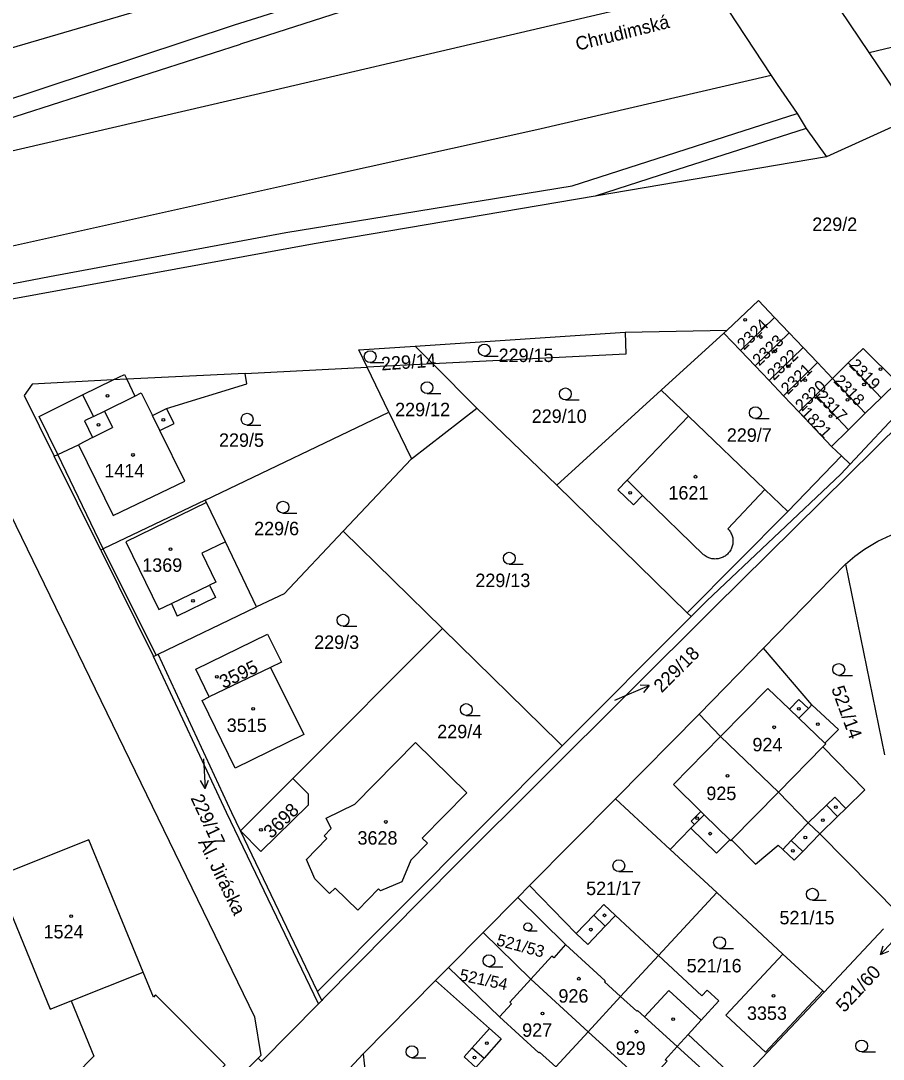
# Model space of a CAD drawing. Extents: x -679220 to -673243, y -1075091 to -1066557.
# Drawn here: x -675950 to -675840.9, y -1071652.9 to -1071521.5 of the extents above; entities that cross this region are included whole.
import ezdxf

# ---------------------------------------------------------------- set-up
doc = ezdxf.new("R2010")
doc.units = 0
for name, color, linetype in [('Hranice parcel', 7, 'Continuous'), ('Parcelní čísla', 7, 'Continuous'), ('Pop  PČ popisy', 7, 'Continuous'), ('Vnitřní kresba', 7, 'Continuous'), ('Značky budov', 7, 'Continuous'), ('Značky kultur', 7, 'Continuous')]:
    doc.layers.add(name, color=color, linetype=linetype)

msp = doc.modelspace()

# ---------------------------------------------------------------- linework, layer by layer
at = {"layer": 'Hranice parcel'}
for p, q in [((-675854.66, -1071559.03), (-675859, -1071563.2)), ((-675854.66, -1071559.03), (-675852.81, -1071560.99)), ((-675900.15, -1071562.66), (-675873.58, -1071560.89)), ((-675873.58, -1071560.89), (-675860.65, -1071560.63)), ((-675869, -1071568.25), (-675861.07, -1071561.03)), ((-675861.07, -1071561.03), (-675860.65, -1071560.63)), ((-675861.07, -1071561.03), (-675859, -1071563.2)), ((-675852.81, -1071560.99), (-675857.14, -1071565.16)), ((-675852.81, -1071560.99), (-675851.06, -1071562.83)), ((-675897.9, -1071564.92), (-675900.15, -1071562.66)), ((-675851.06, -1071562.83), (-675855.37, -1071567.02)), ((-675851.06, -1071562.83), (-675849.25, -1071564.74)), ((-675859, -1071563.2), (-675857.14, -1071565.16)), ((-675921.65, -1071566.11), (-675906.21, -1071565.34)), ((-675897.9, -1071564.92), (-675906.21, -1071565.34)), ((-675903.46, -1071571.03), (-675906.21, -1071565.34)), ((-675897.9, -1071564.92), (-675892.34, -1071570.5)), ((-675857.14, -1071565.16), (-675855.37, -1071567.02)), ((-675849.25, -1071564.74), (-675853.54, -1071568.95)), ((-675849.25, -1071564.74), (-675847.33, -1071566.77)), ((-675847.33, -1071566.77), (-675845.34, -1071564.8)), ((-675841.2, -1071569.22), (-675845.34, -1071564.8)), ((-675855.37, -1071567.02), (-675853.54, -1071568.95)), ((-675847.33, -1071566.77), (-675849.47, -1071568.88)), ((-675843.19, -1071571.17), (-675847.33, -1071566.77)), ((-675882.2, -1071580.25), (-675869, -1071568.25)), ((-675853.54, -1071568.95), (-675851.6, -1071570.98)), ((-675849.47, -1071568.88), (-675851.6, -1071570.98)), ((-675845.32, -1071573.26), (-675849.47, -1071568.88)), ((-675841.2, -1071569.22), (-675843.19, -1071571.17)), ((-675926.7, -1071582.15), (-675903.46, -1071571.03)), ((-675903.46, -1071571.03), (-675900.6, -1071576.95)), ((-675900.6, -1071576.95), (-675892.34, -1071570.5)), ((-675892.34, -1071570.5), (-675882.2, -1071580.25)), ((-675851.6, -1071570.98), (-675847.45, -1071575.35)), ((-675843.19, -1071571.17), (-675845.32, -1071573.26)), ((-675845.32, -1071573.26), (-675847.45, -1071575.35)), ((-675847.45, -1071575.35), (-675846.21, -1071576.54)), ((-675939.91, -1071588.47), (-675945.79, -1071576.58)), ((-675909.23, -1071586.08), (-675900.6, -1071576.95)), ((-675853.01, -1071583.58), (-675846.21, -1071576.54)), ((-675882.2, -1071580.25), (-675865.71, -1071596.42)), ((-675865.71, -1071596.42), (-675853.01, -1071583.58)), ((-675896.66, -1071598.42), (-675909.23, -1071586.08)), ((-675939.91, -1071588.47), (-675933.24, -1071601.95)), ((-675856.06, -1071600.88), (-675845.69, -1071590.25)), ((-675845.69, -1071590.25), (-675840.78, -1071614.39)), ((-675932.64, -1071601.66), (-675920.21, -1071595.68)), ((-675915.61, -1071617.37), (-675896.66, -1071598.42)), ((-675864.22, -1071609.24), (-675856.06, -1071600.88)), ((-675918.42, -1071603.32), (-675926.18, -1071607.06)), ((-675874.81, -1071619.96), (-675864.22, -1071609.24)), ((-675912.49, -1071644.37), (-675881.54, -1071613.27)), ((-675922.23, -1071624), (-675915.61, -1071617.37)), ((-675885.67, -1071630.95), (-675874.81, -1071619.96)), ((-675874.81, -1071619.96), (-675867.88, -1071626.38)), ((-675912.49, -1071644.37), (-675922.23, -1071624)), ((-675848.96, -1071624.39), (-675839.01, -1071634.47)), ((-675867.88, -1071626.38), (-675861.99, -1071631.84)), ((-675887.15, -1071632.45), (-675885.67, -1071630.95)), ((-675891.53, -1071636.88), (-675887.15, -1071632.45)), ((-675861.99, -1071631.84), (-675869.35, -1071639.78)), ((-675861.99, -1071631.84), (-675853.61, -1071639.61)), ((-675840.91, -1071636.43), (-675848.4, -1071644.43)), ((-675895.92, -1071641.31), (-675891.53, -1071636.88)), ((-675891.53, -1071636.88), (-675885.5, -1071642.8)), ((-675853.61, -1071639.61), (-675848.57, -1071644.27)), ((-675943.67, -1071645.52), (-675934.54, -1071641.89)), ((-675897.55, -1071642.97), (-675895.92, -1071641.31)), ((-675906.72, -1071652.25), (-675897.55, -1071642.97)), ((-675885.5, -1071642.8), (-675878.24, -1071649.44)), ((-675911.96, -1071645.47), (-675912.49, -1071644.37)), ((-675848.4, -1071644.43), (-675859.1, -1071655.78)), ((-675848.57, -1071644.27), (-675848.4, -1071644.43)), ((-675911.96, -1071645.47), (-675912.38, -1071645.9)), ((-675870.95, -1071656.1), (-675878.24, -1071649.44)), ((-675915.58, -1071661.71), (-675906.72, -1071652.25))]:
    msp.add_line(p, q, dxfattribs=at)
for points in [[(-675837.15, -1071533.74), (-675838.99, -1071531.01), (-675840.42, -1071528.88), (-675842.72, -1071525.48), (-675850.05, -1071514.58), (-675853.19, -1071509.92), (-675855.42, -1071506.6)], [(-676016.9, -1071547.75), (-675987.28, -1071541.17), (-675968.47, -1071537.02), (-675954.84, -1071532.51), (-675953.23, -1071531.98), (-675923, -1071521.98), (-675892.45, -1071512.39), (-675869.31, -1071507.45)], [(-675837.15, -1071533.74), (-675848.11, -1071538.72), (-675877.36, -1071543.69), (-675912.93, -1071549.73), (-675950.9, -1071556.66), (-675972.74, -1071561.14), (-676014.26, -1071571.02)], [(-675860.65, -1071560.63), (-675856.7, -1071556.88), (-675854.66, -1071559.03)], [(-675873.58, -1071560.89), (-675873.47, -1071563.69), (-675897.9, -1071564.92)], [(-675906.21, -1071565.34), (-675907.27, -1071563.14), (-675900.15, -1071562.66)], [(-675845.34, -1071564.8), (-675843.47, -1071562.95), (-675839.16, -1071567.22), (-675841.2, -1071569.22)], [(-675846.21, -1071576.54), (-675845.1, -1071577.61), (-675838.31, -1071570.35), (-675835.37, -1071567.23), (-675832.35, -1071564.34), (-675831.77, -1071565.57)], [(-675831.77, -1071565.57), (-675862.32, -1071595.73), (-675894.88, -1071628.17), (-675911.82, -1071645.32), (-675911.96, -1071645.47)], [(-675921.65, -1071566.11), (-675936.6, -1071566.86), (-675938.34, -1071566.95), (-675948.6, -1071567.47), (-675949.58, -1071568.92), (-675945.79, -1071576.58)], [(-675945.79, -1071576.58), (-675945.34, -1071576.37), (-675942.72, -1071575.15), (-675938.34, -1071584.12), (-675929.26, -1071579.75), (-675932.44, -1071573.34), (-675930.64, -1071572.45), (-675931.58, -1071570.57), (-675921.44, -1071567.45), (-675921.65, -1071566.11)], [(-676011.87, -1071581.65), (-676010.11, -1071577.99), (-675962.74, -1071567.26), (-675958.61, -1071569.02), (-675920.48, -1071647.57), (-675919.65, -1071652.44), (-675920, -1071652.79)], [(-675853.01, -1071583.58), (-675855.88, -1071580.82), (-675865.56, -1071571.54), (-675869, -1071568.25)], [(-675926.7, -1071582.15), (-675939.59, -1071588.32), (-675939.91, -1071588.47)], [(-675920.21, -1071595.68), (-675924.13, -1071587.42), (-675926.55, -1071582.46), (-675926.7, -1071582.15)], [(-675845.69, -1071590.25), (-675844.52, -1071589.23), (-675843.28, -1071588.35), (-675841.6, -1071587.37), (-675839.97, -1071586.6), (-675838.55, -1071586.06), (-675836.65, -1071585.68), (-675834.32, -1071585.37), (-675832.14, -1071585.35), (-675828.3, -1071585.95), (-675826.58, -1071586.56), (-675824.62, -1071587.52), (-675822.57, -1071588.81), (-675821.2, -1071589.94), (-675818.99, -1071592.52)], [(-675909.23, -1071586.08), (-675916.71, -1071594), (-675920.21, -1071595.68)], [(-675881.54, -1071613.27), (-675865.23, -1071596.89), (-675865.71, -1071596.42)], [(-675881.54, -1071613.27), (-675881.98, -1071612.85), (-675896.66, -1071598.42)], [(-675926.18, -1071607.06), (-675927.9, -1071603.57), (-675918.8, -1071599.11), (-675917.06, -1071602.66), (-675918.42, -1071603.32)], [(-675848.96, -1071624.39), (-675846.7, -1071622.19), (-675845.66, -1071621.18), (-675843.24, -1071618.82), (-675848.55, -1071613.37), (-675848.2, -1071613.02), (-675848.3, -1071612.91), (-675846.58, -1071611.18), (-675849.97, -1071608.07), (-675856.06, -1071600.88)], [(-675933.24, -1071601.95), (-675932.91, -1071601.79), (-675932.64, -1071601.66)], [(-675912.38, -1071645.9), (-675923.99, -1071621.69), (-675933.24, -1071601.95)], [(-675922.23, -1071624), (-675923.31, -1071621.75), (-675932.64, -1071601.66)], [(-675918.42, -1071603.32), (-675914.23, -1071611.83), (-675922.89, -1071616.07), (-675927.1, -1071607.52), (-675926.18, -1071607.06)], [(-675864.22, -1071609.24), (-675861.5, -1071612.08), (-675854.19, -1071619.12), (-675850.4, -1071623), (-675848.96, -1071624.39)], [(-675910.24, -1071631.25), (-675910.96, -1071631.94), (-675912.82, -1071630.1), (-675913.89, -1071627.65), (-675911.29, -1071624.98), (-675911.64, -1071624.63), (-675910.74, -1071623.7), (-675911.39, -1071622.42), (-675907.78, -1071620.63), (-675900.1, -1071612.84), (-675893.61, -1071619.2), (-675899.23, -1071624.94), (-675898.59, -1071625.56), (-675900.68, -1071627.72), (-675901.81, -1071630.46), (-675904.53, -1071631.6), (-675904.77, -1071631.37), (-675907.4, -1071634.06), (-675910.24, -1071631.25)], [(-675915.61, -1071617.37), (-675913.67, -1071619.34), (-675913.68, -1071620.76), (-675919.67, -1071626.63), (-675922.23, -1071624)], [(-675867.88, -1071626.38), (-675865.25, -1071623.69), (-675862, -1071626.86), (-675860.32, -1071625.16), (-675860.22, -1071625.26), (-675860.11, -1071625.15), (-675857.08, -1071628.23), (-675854.2, -1071625.81), (-675853.62, -1071626.36), (-675852.18, -1071627.74), (-675851.11, -1071626.62), (-675848.96, -1071624.39)], [(-675934.54, -1071641.89), (-675941.42, -1071625.16), (-675953.19, -1071629.84), (-675946.31, -1071646.57), (-675943.67, -1071645.52)], [(-675869.35, -1071639.78), (-675874.81, -1071634.71), (-675876.28, -1071633.35), (-675877.55, -1071634.69), (-675879.76, -1071637.01), (-675885.67, -1071630.95)], [(-675887.15, -1071632.45), (-675881.1, -1071638.42), (-675882.61, -1071640.07), (-675882.83, -1071639.87), (-675885.5, -1071642.8)], [(-675878.24, -1071649.44), (-675874.16, -1071644.98), (-675869.35, -1071639.78)], [(-675860.11, -1071654.88), (-675865.58, -1071649.78), (-675863.95, -1071647.98), (-675861.72, -1071645.51), (-675863.2, -1071644.17), (-675863.89, -1071644.9), (-675869.35, -1071639.78)], [(-675848.57, -1071644.27), (-675855.83, -1071652.04), (-675860.84, -1071647.36), (-675853.61, -1071639.61)], [(-675943.67, -1071645.52), (-675940.78, -1071652.55), (-675947.61, -1071659.51), (-675938.7, -1071668.46), (-675924.16, -1071653.64), (-675932.99, -1071644.79), (-675933.25, -1071645.05), (-675934.54, -1071641.89)], [(-675885.5, -1071642.8), (-675888.18, -1071645.72), (-675887.96, -1071645.93), (-675889.47, -1071647.57), (-675895.92, -1071641.31)], [(-675897.55, -1071642.97), (-675890.75, -1071649.02), (-675892.92, -1071651.46), (-675893.92, -1071652.6), (-675892.45, -1071653.96), (-675887.04, -1071658.99)], [(-675920, -1071652.79), (-675919.58, -1071653.19), (-675912.38, -1071645.9)], [(-675887.04, -1071658.99), (-675882.32, -1071653.9), (-675878.24, -1071649.44)], [(-675906.72, -1071652.25), (-675906.47, -1071654.59), (-675893.87, -1071666.36)], [(-675870.95, -1071656.1), (-675868.27, -1071653.18), (-675868.49, -1071652.98), (-675866.99, -1071651.33), (-675861.47, -1071656.34)], [(-675976.71, -1071708.75), (-675975.19, -1071708.41), (-675920, -1071652.79)]]:
    msp.add_lwpolyline(points, dxfattribs=at)
at = {"layer": 'Pop  PČ popisy'}
for p, q in [((-675873.31, -1071606.81), (-675870.55, -1071605.64)), ((-675870.55, -1071605.64), (-675871.67, -1071605.57)), ((-675870.55, -1071605.64), (-675871.27, -1071606.49)), ((-675874.87, -1071607.47), (-675873.31, -1071606.81)), ((-675926.91, -1071614.88), (-675926.87, -1071615.64)), ((-675926.87, -1071615.64), (-675926.71, -1071618.64)), ((-675926.71, -1071618.64), (-675927.27, -1071617.66)), ((-675926.71, -1071618.64), (-675926.27, -1071617.61)), ((-675839.21, -1071637.45), (-675841.26, -1071639.65)), ((-675841.26, -1071639.65), (-675840.94, -1071638.57)), ((-675841.26, -1071639.65), (-675840.21, -1071639.25))]:
    msp.add_line(p, q, dxfattribs=at)
at = {"layer": 'Vnitřní kresba'}
for p, q in [((-675892.04, -1071514.69), (-675922.22, -1071524.46)), ((-675923.04, -1071516.66), (-675954.99, -1071526.05)), ((-675889.32, -1071523.57), (-675862.44, -1071517.25)), ((-675862.44, -1071517.25), (-675855.08, -1071528.41)), ((-675842.72, -1071525.48), (-675824.71, -1071521.21)), ((-675920.42, -1071530.83), (-675889.32, -1071523.57)), ((-675968.39, -1071539.22), (-675922.22, -1071524.46)), ((-675855.08, -1071528.41), (-675884.76, -1071535.3)), ((-675855.08, -1071528.41), (-675854.32, -1071529.54)), ((-675854.32, -1071529.54), (-675851.82, -1071533.23)), ((-675967.04, -1071541.6), (-675920.42, -1071530.83)), ((-675859.7, -1071535.77), (-675851.82, -1071533.23)), ((-675851.82, -1071533.23), (-675850.66, -1071535.1)), ((-675884.76, -1071535.3), (-675911.59, -1071541.24)), ((-675850.66, -1071535.1), (-675859.22, -1071537.85)), ((-675850.66, -1071535.1), (-675848.11, -1071538.72)), ((-675868.33, -1071538.55), (-675859.7, -1071535.77)), ((-675859.22, -1071537.85), (-675867.82, -1071540.62)), ((-675880.29, -1071542.39), (-675868.33, -1071538.55)), ((-675867.82, -1071540.62), (-675877.36, -1071543.69)), ((-675911.59, -1071541.24), (-675964.48, -1071553.01)), ((-675909.48, -1071547.14), (-675880.29, -1071542.39)), ((-675916.49, -1071548.28), (-675909.48, -1071547.14)), ((-675946.38, -1071553.87), (-675916.49, -1071548.28)), ((-675965.01, -1071557.35), (-675946.38, -1071553.87)), ((-675942.22, -1071568.83), (-675938.34, -1071566.95)), ((-675938.34, -1071566.95), (-675936.9, -1071566.25)), ((-675936.9, -1071566.25), (-675936.6, -1071566.86)), ((-675936.6, -1071566.86), (-675935.58, -1071568.98)), ((-675947.69, -1071571.56), (-675942.22, -1071568.83)), ((-675942.22, -1071568.83), (-675940.84, -1071571.57)), ((-675939.44, -1071570.89), (-675935.58, -1071568.98)), ((-675935.58, -1071568.98), (-675934.79, -1071568.59)), ((-675934.79, -1071568.59), (-675933.37, -1071571.45)), ((-675940.84, -1071571.57), (-675939.44, -1071570.89)), ((-675939.44, -1071570.89), (-675938.41, -1071572.98)), ((-675933.37, -1071571.45), (-675931.58, -1071570.57)), ((-675945.34, -1071576.37), (-675947.69, -1071571.56)), ((-675940.84, -1071571.57), (-675941.95, -1071572.12)), ((-675941.95, -1071572.12), (-675940.96, -1071574.22)), ((-675932.44, -1071573.34), (-675933.37, -1071571.45)), ((-675873.33, -1071579.64), (-675865.56, -1071571.54)), ((-675940.96, -1071574.22), (-675938.41, -1071572.98)), ((-675940.96, -1071574.22), (-675942.72, -1071575.15)), ((-675939.59, -1071588.32), (-675945.34, -1071576.37)), ((-675845.1, -1071577.61), (-675846.3, -1071578.89)), ((-675863.25, -1071594.89), (-675846.3, -1071578.89)), ((-675874.49, -1071580.85), (-675873.33, -1071579.64)), ((-675873.33, -1071579.64), (-675871.36, -1071581.56)), ((-675872.53, -1071582.76), (-675874.49, -1071580.85)), ((-675871.36, -1071581.56), (-675872.53, -1071582.76)), ((-675863.65, -1071589.06), (-675871.36, -1071581.56)), ((-675855.88, -1071580.82), (-675860.59, -1071585.77)), ((-675926.55, -1071582.46), (-675936.72, -1071587.42)), ((-675936.72, -1071587.42), (-675932.55, -1071595.99)), ((-675924.13, -1071587.42), (-675927.13, -1071588.88)), ((-675932.91, -1071601.79), (-675939.59, -1071588.32)), ((-675927.13, -1071588.88), (-675925.34, -1071592.54)), ((-675930.97, -1071595.24), (-675926.14, -1071592.93)), ((-675925.34, -1071592.54), (-675926.14, -1071592.93)), ((-675926.14, -1071592.93), (-675925.39, -1071594.47)), ((-675925.39, -1071594.47), (-675930.26, -1071596.85)), ((-675932.55, -1071595.99), (-675930.97, -1071595.24)), ((-675930.97, -1071595.24), (-675930.26, -1071596.85)), ((-675863.25, -1071594.89), (-675865.23, -1071596.89)), ((-675855.53, -1071605.99), (-675861.5, -1071612.08)), ((-675855.53, -1071605.99), (-675852.78, -1071608.62)), ((-675852.78, -1071608.62), (-675851.59, -1071607.37)), ((-675851.59, -1071607.37), (-675850.39, -1071608.52)), ((-675852.78, -1071608.62), (-675851.59, -1071609.76)), ((-675850.39, -1071608.52), (-675851.59, -1071609.76)), ((-675850.39, -1071608.52), (-675849.97, -1071608.07)), ((-675851.59, -1071609.76), (-675848.3, -1071612.91)), ((-675861.5, -1071612.08), (-675867.46, -1071618.15)), ((-675854.19, -1071619.12), (-675848.55, -1071613.37)), ((-675867.46, -1071618.15), (-675864, -1071621.55)), ((-675860.11, -1071625.15), (-675854.19, -1071619.12)), ((-675850.4, -1071623), (-675848.1, -1071620.75)), ((-675848.1, -1071620.75), (-675847.06, -1071619.74)), ((-675848.1, -1071620.75), (-675846.7, -1071622.19)), ((-675847.06, -1071619.74), (-675845.66, -1071621.18)), ((-675864, -1071621.55), (-675865.23, -1071622.8)), ((-675864.8, -1071623.22), (-675863.57, -1071621.97)), ((-675864, -1071621.55), (-675863.57, -1071621.97)), ((-675863.57, -1071621.97), (-675860.32, -1071625.16)), ((-675865.25, -1071623.69), (-675864.8, -1071623.22)), ((-675865.23, -1071622.8), (-675864.8, -1071623.22)), ((-675852.55, -1071625.24), (-675850.4, -1071623)), ((-675853.62, -1071626.36), (-675852.55, -1071625.24)), ((-675852.55, -1071625.24), (-675851.11, -1071626.62)), ((-675876.11, -1071636.07), (-675877.55, -1071634.69)), ((-675874.81, -1071634.71), (-675876.11, -1071636.07)), ((-675876.11, -1071636.07), (-675878.31, -1071638.39)), ((-675878.31, -1071638.39), (-675879.76, -1071637.01)), ((-675881.1, -1071638.42), (-675876.08, -1071643.01)), ((-675876.08, -1071643.01), (-675876.19, -1071643.12)), ((-675876.19, -1071643.12), (-675874.16, -1071644.98)), ((-675871.12, -1071647.55), (-675868.04, -1071644.24)), ((-675868.04, -1071644.24), (-675863.95, -1071647.98)), ((-675874.16, -1071644.98), (-675872.1, -1071646.85)), ((-675872.1, -1071646.85), (-675872, -1071646.74)), ((-675872, -1071646.74), (-675871.12, -1071647.55)), ((-675889.47, -1071647.57), (-675884.49, -1071652.12)), ((-675871.12, -1071647.55), (-675866.99, -1071651.33)), ((-675890.75, -1071649.02), (-675889.25, -1071650.34)), ((-675865.58, -1071649.78), (-675866.99, -1071651.33)), ((-675889.25, -1071650.34), (-675891.42, -1071652.79)), ((-675892.92, -1071651.46), (-675891.42, -1071652.79)), ((-675884.49, -1071652.12), (-675884.39, -1071652.01)), ((-675884.39, -1071652.01), (-675882.32, -1071653.9)), ((-675891.42, -1071652.79), (-675892.45, -1071653.96))]:
    msp.add_line(p, q, dxfattribs=at)
msp.add_lwpolyline([(-675860.59, -1071585.77), (-675860.5, -1071585.87), (-675860.41, -1071585.97), (-675860.34, -1071586.07), (-675860.26, -1071586.19), (-675860.2, -1071586.3), (-675860.14, -1071586.42), (-675860.09, -1071586.54), (-675860.04, -1071586.67), (-675860, -1071586.79), (-675859.97, -1071586.92), (-675859.95, -1071587.06), (-675859.94, -1071587.19), (-675859.93, -1071587.32), (-675859.93, -1071587.45), (-675859.94, -1071587.58), (-675859.96, -1071587.72), (-675859.98, -1071587.85), (-675860.02, -1071587.98), (-675860.06, -1071588.1), (-675860.1, -1071588.23), (-675860.16, -1071588.35), (-675860.22, -1071588.46), (-675860.29, -1071588.58), (-675860.36, -1071588.69), (-675860.45, -1071588.79), (-675860.53, -1071588.89), (-675860.63, -1071588.99), (-675860.72, -1071589.07), (-675860.83, -1071589.16), (-675860.94, -1071589.23), (-675861.05, -1071589.3), (-675861.17, -1071589.37), (-675861.29, -1071589.42), (-675861.41, -1071589.47), (-675861.54, -1071589.51), (-675861.66, -1071589.55), (-675861.79, -1071589.57), (-675861.93, -1071589.59), (-675862.06, -1071589.6), (-675862.19, -1071589.61), (-675862.32, -1071589.6), (-675862.46, -1071589.59), (-675862.59, -1071589.57), (-675862.72, -1071589.54), (-675862.84, -1071589.51), (-675862.97, -1071589.47), (-675863.09, -1071589.41), (-675863.21, -1071589.36), (-675863.33, -1071589.29), (-675863.44, -1071589.22), (-675863.55, -1071589.14), (-675863.65, -1071589.06)], dxfattribs=at)
at = {"layer": 'Značky budov'}
for centre in [(-675858.4, -1071559.34), (-675856.41, -1071561.51), (-675854.61, -1071563.32), (-675852.89, -1071565.21), (-675841.27, -1071565.57), (-675850.81, -1071566.97), (-675843.35, -1071567.51), (-675939.06, -1071568.95), (-675845.43, -1071569.45), (-675931.99, -1071571.98), (-675847.6, -1071571.53), (-675940.2, -1071572.63), (-675935.83, -1071576.44), (-675864.67, -1071579.19), (-675872.95, -1071581.22), (-675931.09, -1071588.35), (-675928.24, -1071594.89), (-675925.23, -1071604.51), (-675920.62, -1071608.58), (-675851.59, -1071608.58), (-675849.19, -1071610.52), (-675854.71, -1071610.91), (-675860.63, -1071617.04), (-675846.92, -1071621.01), (-675864.45, -1071622.42), (-675903.85, -1071622.89), (-675848.55, -1071622.67), (-675919.64, -1071623.9), (-675862.82, -1071624.37), (-675850.78, -1071624.85), (-675852.35, -1071626.55), (-675943.66, -1071634.8), (-675876.19, -1071634.71), (-675877.9, -1071636.52), (-675879.43, -1071642.73), (-675854.8, -1071644.89), (-675884.02, -1071647.14), (-675867.51, -1071647.84), (-675872.15, -1071649.43), (-675891.08, -1071650.88), (-675892.63, -1071652.69)]:
    msp.add_circle(centre, 0.175, dxfattribs=at)
at = {"layer": 'Značky kultur'}
for p, q in [((-675891.37, -1071563.92), (-675889.62, -1071563.92)), ((-675905.83, -1071564.74), (-675904.08, -1071564.74)), ((-675898.63, -1071568.67), (-675896.88, -1071568.67)), ((-675881.13, -1071569.46), (-675879.38, -1071569.46)), ((-675857.09, -1071571.84), (-675855.34, -1071571.84)), ((-675921.39, -1071572.66), (-675919.64, -1071572.66)), ((-675916.87, -1071583.8), (-675915.12, -1071583.8)), ((-675888.23, -1071590.26), (-675886.48, -1071590.26)), ((-675909.26, -1071598.11), (-675907.51, -1071598.11)), ((-675846.55, -1071604.34), (-675844.8, -1071604.34)), ((-675893.67, -1071609.41), (-675891.92, -1071609.41)), ((-675874.37, -1071629.18), (-675872.62, -1071629.18)), ((-675849.88, -1071632.79), (-675848.13, -1071632.79)), ((-675885.88, -1071636.68), (-675884.7, -1071636.68)), ((-675861.63, -1071638.91), (-675859.88, -1071638.91)), ((-675890.8, -1071641.21), (-675889.05, -1071641.21)), ((-675843.65, -1071651.99), (-675841.9, -1071651.99)), ((-675900.54, -1071652.73), (-675898.79, -1071652.73))]:
    msp.add_line(p, q, dxfattribs=at)
for centre, radius in [((-675891.37, -1071563.17), 0.75), ((-675905.83, -1071563.99), 0.75), ((-675898.63, -1071567.92), 0.75), ((-675881.13, -1071568.71), 0.75), ((-675857.09, -1071571.09), 0.75), ((-675921.39, -1071571.91), 0.75), ((-675916.87, -1071583.05), 0.75), ((-675888.23, -1071589.51), 0.75), ((-675909.26, -1071597.36), 0.75), ((-675846.55, -1071603.59), 0.75), ((-675893.67, -1071608.66), 0.75), ((-675874.37, -1071628.43), 0.75), ((-675849.88, -1071632.04), 0.75), ((-675885.88, -1071636.18), 0.502), ((-675861.63, -1071638.16), 0.75), ((-675890.8, -1071640.46), 0.75), ((-675900.54, -1071651.98), 0.75), ((-675843.65, -1071651.24), 0.75)]:
    msp.add_circle(centre, radius, dxfattribs=at)

# ---------------------------------------------------------------- texts
at = {"layer": 'Parcelní čísla'}
for s, p in [('229/2', (-675849.9, -1071548.09)), ('229/15', (-675889.58, -1071564.68)), ('229/12', (-675902.67, -1071571.54)), ('229/10', (-675885.39, -1071572.38)), ('229/5', (-675924.95, -1071575.41)), ('229/7', (-675860.71, -1071574.77)), ('1414', (-675939.45, -1071579.29)), ('1621', (-675868.1, -1071582.08)), ('229/6', (-675920.51, -1071586.6)), ('1369', (-675934.66, -1071591.23)), ('229/13', (-675892.52, -1071593.16)), ('229/3', (-675912.91, -1071600.99)), ('3515', (-675923.97, -1071611.5)), ('229/4', (-675897.34, -1071612.29)), ('924', (-675857.47, -1071613.95)), ('925', (-675863.3, -1071620.12)), ('3628', (-675907.43, -1071625.76)), ('521/17', (-675878.51, -1071632.15)), ('521/15', (-675854.05, -1071635.85)), ('1524', (-675947.14, -1071637.63)), ('521/16', (-675865.79, -1071641.93)), ('926', (-675882.01, -1071645.76)), ('3353', (-675858.16, -1071647.94)), ('927', (-675886.6, -1071650.08)), ('929', (-675874.77, -1071652.37))]:
    msp.add_text(s, height=1.7, dxfattribs=at).set_placement(p)
for s, height, rotation, p in [('2324', 1.5, 44, (-675858.54, -1071563.24)), ('2323', 1.5, 44, (-675856.6, -1071565.25)), ('2322', 1.5, 44, (-675854.76, -1071567.09)), ('229/14', 1.7, 4, (-675904.38, -1071565.75)), ('2319', 1.5, 314, (-675845.32, -1071565.13)), ('2321', 1.5, 44, (-675853, -1071568.88)), ('2320', 1.5, 44, (-675851.19, -1071571)), ('2318', 1.5, 314, (-675847.31, -1071567.14)), ('2317', 1.5, 314, (-675849.51, -1071569.15)), ('1821', 1.5, 314, (-675851.46, -1071571.24)), ('229/18', 1.7, 45, (-675868.95, -1071606.63)), ('3595', 1.7, 26, (-675924.38, -1071606.06)), ('521/14', 1.7, 290, (-675847.52, -1071606.01)), ('229/17', 1.7, 295, (-675928.58, -1071619.86)), ('3698', 1.7, 44, (-675918.33, -1071625.08)), ('521/53', 1.5, 345, (-675889.95, -1071638.48)), ('521/54', 1.5, 348, (-675894.62, -1071642.93)), ('521/60', 1.7, 47, (-675845.85, -1071647.1))]:
    msp.add_text(s, height=height, rotation=rotation, dxfattribs=at).set_placement(p)
at = {"layer": 'Pop  PČ popisy'}
for s, rotation, p in [('Chrudimská', 14, (-675879.61, -1071525.29)), ('Al. Jiráska', 296, (-675927.61, -1071625.44))]:
    msp.add_text(s, height=1.7, rotation=rotation, dxfattribs=at).set_placement(p)

doc.saveas('drawing.dxf')
